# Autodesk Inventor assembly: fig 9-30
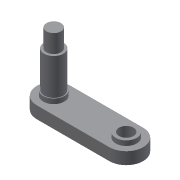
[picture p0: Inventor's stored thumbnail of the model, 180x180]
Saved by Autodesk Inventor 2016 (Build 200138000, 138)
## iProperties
Shininess: 64.0
Length Units: 11269
Angle Units: 11279
Time Units: 11290
Mass Units: 11283
Length Display Precision: 3
Angle Display Precision: 2
Created: 2002-01
Part Number: fig 9-30
Document SubType Name: Assembly
Designer: ***
Density: 0.0
Volumn: 0.0
Area: 0.0
PropertySet Name: Model Information
Control State: 0
Master: False
Checked Out: False
Author: ***
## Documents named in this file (3)
- D:\KAVITA\Autodesk Inventor_ 2016 Project_Kavita\Inventor_Part Files\Inventor_2016_Part\c09_Inv_2016\c09_inv_2016_prt\fig 9-34.iam
- D:\KAVITA\Autodesk Inventor_ 2016 Project_Kavita\Inventor_Part Files\Inventor_2016_Part\c09_Inv_2016\c09_inv_2016_prt\Part5.ipt
- D:\KAVITA\Autodesk Inventor_ 2016 Project_Kavita\Inventor_Part Files\Inventor_2016_Part\c09_Inv_2016\c09_inv_2016_prt\Part6.ipt
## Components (2 placed, 2 different names)
1. Part5:1 — Insert:1
2. Part6:1 — Insert:1
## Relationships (1: Insert 1)
- Insert:1: Part5:1 ↔ Part6:1
